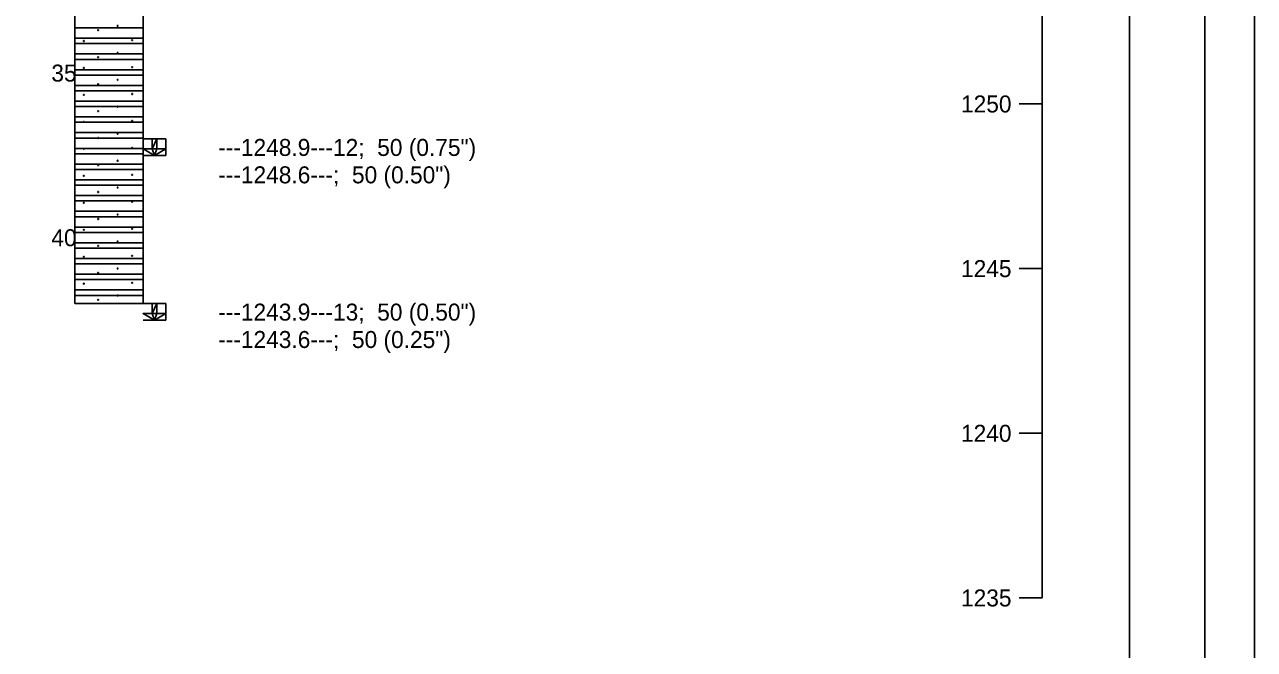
# Model space of a CAD drawing. Extents: x 2150148.6 to 2150220.1, y 143803.7 to 143875.1.
# Drawn here: x 2150191.59 to 2150200.57, y 143815.4 to 143819.96 of the extents above; entities that cross this region are included whole.
import ezdxf

# ---------------------------------------------------------------- set-up
doc = ezdxf.new("R2010")
doc.units = 0
for name, color, linetype in [('Default', 7, 'Continuous'), ('SHT_Plot_Shape_Full', 7, 'Continuous'), ('SHT_Plot_Shape_Half', 7, 'Continuous'), ('SHT_Sheet_Border', 7, 'Continuous')]:
    doc.layers.add(name, color=color, linetype=linetype)

msp = doc.modelspace()

# ---------------------------------------------------------------- linework, layer by layer
at = {"layer": 'Default'}
msp.add_line((2150199.0247, 143815.7727), (2150199.0247, 143828.9938), dxfattribs=at)
for points in [[(2150191.9604, 143828.0174), (2150191.9604, 143817.9213)], [(2150192.4604, 143828.0174), (2150192.4604, 143817.9213)], [(2150191.9604, 143819.9337), (2150192.4604, 143819.9337)], [(2150192.1355, 143819.9172), (2150192.1338, 143819.9201), (2150192.1306, 143819.9201), (2150192.1289, 143819.9173), (2150192.1306, 143819.9144), (2150192.1338, 143819.9144), (2150192.1355, 143819.9172)], [(2150192.2781, 143819.9491), (2150192.2764, 143819.9519), (2150192.2731, 143819.9519), (2150192.2715, 143819.9491), (2150192.2731, 143819.9463), (2150192.2764, 143819.9463), (2150192.2781, 143819.9491)], [(2150191.9604, 143819.8582), (2150192.4604, 143819.8582)], [(2150192.0308, 143819.8383), (2150192.0292, 143819.8411), (2150192.0259, 143819.8411), (2150192.0243, 143819.8383), (2150192.0259, 143819.8354), (2150192.0292, 143819.8354), (2150192.0308, 143819.8383)], [(2150192.3836, 143819.8448), (2150192.3819, 143819.8477), (2150192.3787, 143819.8477), (2150192.377, 143819.8448), (2150192.3787, 143819.8419), (2150192.3819, 143819.8419), (2150192.3836, 143819.8448)], [(2150191.9604, 143819.8188), (2150192.4604, 143819.8188)], [(2150191.9604, 143819.7434), (2150192.4604, 143819.7434)], [(2150192.2781, 143819.7522), (2150192.2764, 143819.7551), (2150192.2731, 143819.7551), (2150192.2715, 143819.7522), (2150192.2731, 143819.7494), (2150192.2764, 143819.7494), (2150192.2781, 143819.7522)], [(2150191.9604, 143819.704), (2150192.4604, 143819.704)], [(2150192.0308, 143819.6414), (2150192.0292, 143819.6442), (2150192.0259, 143819.6442), (2150192.0243, 143819.6414), (2150192.0259, 143819.6385), (2150192.0292, 143819.6385), (2150192.0308, 143819.6414)], [(2150192.1355, 143819.7204), (2150192.1338, 143819.7232), (2150192.1306, 143819.7232), (2150192.1289, 143819.7204), (2150192.1306, 143819.7175), (2150192.1338, 143819.7175), (2150192.1355, 143819.7204)], [(2150192.3836, 143819.6479), (2150192.3819, 143819.6508), (2150192.3787, 143819.6508), (2150192.377, 143819.6479), (2150192.3787, 143819.6451), (2150192.3819, 143819.6451), (2150192.3836, 143819.6479)], [(2150191.9604, 143819.6286), (2150192.4604, 143819.6286)], [(2150191.9604, 143819.5892), (2150192.4604, 143819.5892)], [(2150192.2781, 143819.5554), (2150192.2764, 143819.5582), (2150192.2731, 143819.5582), (2150192.2715, 143819.5554), (2150192.2731, 143819.5526), (2150192.2764, 143819.5526), (2150192.2781, 143819.5554)], [(2150191.9604, 143819.5137), (2150192.4604, 143819.5137)], [(2150191.9604, 143819.4744), (2150192.4604, 143819.4744)], [(2150192.1355, 143819.5235), (2150192.1338, 143819.5264), (2150192.1306, 143819.5264), (2150192.1289, 143819.5236), (2150192.1306, 143819.5207), (2150192.1338, 143819.5207), (2150192.1355, 143819.5235)], [(2150191.9604, 143819.3989), (2150192.4604, 143819.3989)], [(2150192.0308, 143819.4446), (2150192.0292, 143819.4474), (2150192.0259, 143819.4474), (2150192.0243, 143819.4446), (2150192.0259, 143819.4417), (2150192.0292, 143819.4417), (2150192.0308, 143819.4446)], [(2150192.3836, 143819.4511), (2150192.3819, 143819.454), (2150192.3787, 143819.454), (2150192.377, 143819.4511), (2150192.3787, 143819.4482), (2150192.3819, 143819.4482), (2150192.3836, 143819.4511)], [(2150199.0247, 143819.3785), (2150198.858, 143819.3785)], [(2150191.9604, 143819.3595), (2150192.4604, 143819.3595)], [(2150191.9604, 143819.2841), (2150192.4604, 143819.2841)], [(2150192.1355, 143819.3267), (2150192.1338, 143819.3295), (2150192.1306, 143819.3295), (2150192.1289, 143819.3267), (2150192.1306, 143819.3238), (2150192.1338, 143819.3238), (2150192.1355, 143819.3267)], [(2150192.2781, 143819.3585), (2150192.2764, 143819.3614), (2150192.2731, 143819.3614), (2150192.2715, 143819.3585), (2150192.2731, 143819.3557), (2150192.2764, 143819.3557), (2150192.2781, 143819.3585)], [(2150191.9604, 143819.2447), (2150192.4604, 143819.2447)], [(2150192.0308, 143819.2477), (2150192.0292, 143819.2505), (2150192.0259, 143819.2505), (2150192.0243, 143819.2477), (2150192.0259, 143819.2448), (2150192.0292, 143819.2448), (2150192.0308, 143819.2477)], [(2150192.3836, 143819.2542), (2150192.3819, 143819.2571), (2150192.3787, 143819.2571), (2150192.377, 143819.2542), (2150192.3787, 143819.2514), (2150192.3819, 143819.2514), (2150192.3836, 143819.2542)], [(2150191.9604, 143819.1692), (2150192.4604, 143819.1692)], [(2150191.9604, 143819.1299), (2150192.4604, 143819.1299)], [(2150192.1355, 143819.1298), (2150192.1338, 143819.1327), (2150192.1306, 143819.1327), (2150192.1289, 143819.1299), (2150192.1306, 143819.127), (2150192.1338, 143819.127), (2150192.1355, 143819.1298)], [(2150192.2781, 143819.1617), (2150192.2764, 143819.1645), (2150192.2731, 143819.1645), (2150192.2715, 143819.1617), (2150192.2731, 143819.1589), (2150192.2764, 143819.1589), (2150192.2781, 143819.1617)], [(2150192.4604, 143819.1232), (2150192.6271, 143819.1232)], [(2150192.6271, 143819.003), (2150192.6271, 143819.1232)], [(2150191.9604, 143819.0544), (2150192.4604, 143819.0544)], [(2150191.9604, 143819.015), (2150192.4604, 143819.015)], [(2150192.0308, 143819.0509), (2150192.0292, 143819.0537), (2150192.0259, 143819.0537), (2150192.0243, 143819.0509), (2150192.0259, 143819.048), (2150192.0292, 143819.048), (2150192.0308, 143819.0509)], [(2150192.3836, 143819.0574), (2150192.3819, 143819.0603), (2150192.3787, 143819.0603), (2150192.377, 143819.0574), (2150192.3787, 143819.0545), (2150192.3819, 143819.0545), (2150192.3836, 143819.0574)], [(2150191.9604, 143818.9396), (2150192.4604, 143818.9396)], [(2150192.1355, 143818.933), (2150192.1338, 143818.9358), (2150192.1306, 143818.9358), (2150192.1289, 143818.933), (2150192.1306, 143818.9301), (2150192.1338, 143818.9301), (2150192.1355, 143818.933)], [(2150192.2781, 143818.9648), (2150192.2764, 143818.9677), (2150192.2731, 143818.9677), (2150192.2715, 143818.9648), (2150192.2731, 143818.962), (2150192.2764, 143818.962), (2150192.2781, 143818.9648)], [(2150192.4604, 143819.003), (2150192.6271, 143819.003)], [(2150191.9604, 143818.9002), (2150192.4604, 143818.9002)], [(2150192.0308, 143818.854), (2150192.0292, 143818.8568), (2150192.0259, 143818.8568), (2150192.0243, 143818.854), (2150192.0259, 143818.8511), (2150192.0292, 143818.8511), (2150192.0308, 143818.854)], [(2150192.3836, 143818.8605), (2150192.3819, 143818.8634), (2150192.3787, 143818.8634), (2150192.377, 143818.8605), (2150192.3787, 143818.8577), (2150192.3819, 143818.8577), (2150192.3836, 143818.8605)], [(2150191.9604, 143818.8248), (2150192.4604, 143818.8248)], [(2150191.9604, 143818.7854), (2150192.4604, 143818.7854)], [(2150192.2781, 143818.768), (2150192.2764, 143818.7708), (2150192.2731, 143818.7708), (2150192.2715, 143818.768), (2150192.2731, 143818.7652), (2150192.2764, 143818.7652), (2150192.2781, 143818.768)], [(2150191.9604, 143818.7099), (2150192.4604, 143818.7099)], [(2150191.9604, 143818.6706), (2150192.4604, 143818.6706)], [(2150192.0308, 143818.6572), (2150192.0292, 143818.66), (2150192.0259, 143818.66), (2150192.0243, 143818.6572), (2150192.0259, 143818.6543), (2150192.0292, 143818.6543), (2150192.0308, 143818.6572)], [(2150192.1355, 143818.7361), (2150192.1338, 143818.739), (2150192.1306, 143818.739), (2150192.1289, 143818.7362), (2150192.1306, 143818.7333), (2150192.1338, 143818.7333), (2150192.1355, 143818.7361)], [(2150192.3836, 143818.6637), (2150192.3819, 143818.6666), (2150192.3787, 143818.6666), (2150192.377, 143818.6637), (2150192.3787, 143818.6608), (2150192.3819, 143818.6608), (2150192.3836, 143818.6637)], [(2150191.9604, 143818.5951), (2150192.4604, 143818.5951)], [(2150192.2781, 143818.5711), (2150192.2764, 143818.574), (2150192.2731, 143818.574), (2150192.2715, 143818.5711), (2150192.2731, 143818.5683), (2150192.2764, 143818.5683), (2150192.2781, 143818.5711)], [(2150191.9604, 143818.5557), (2150192.4604, 143818.5557)], [(2150191.9604, 143818.4803), (2150192.4604, 143818.4803)], [(2150192.1355, 143818.5393), (2150192.1338, 143818.5421), (2150192.1306, 143818.5421), (2150192.1289, 143818.5393), (2150192.1306, 143818.5364), (2150192.1338, 143818.5364), (2150192.1355, 143818.5393)], [(2150191.9604, 143818.4409), (2150192.4604, 143818.4409)], [(2150192.0308, 143818.4603), (2150192.0292, 143818.4631), (2150192.0259, 143818.4631), (2150192.0243, 143818.4603), (2150192.0259, 143818.4574), (2150192.0292, 143818.4574), (2150192.0308, 143818.4603)], [(2150192.3836, 143818.4668), (2150192.3819, 143818.4697), (2150192.3787, 143818.4697), (2150192.377, 143818.4668), (2150192.3787, 143818.464), (2150192.3819, 143818.464), (2150192.3836, 143818.4668)], [(2150191.9604, 143818.3654), (2150192.4604, 143818.3654)], [(2150191.9604, 143818.3261), (2150192.4604, 143818.3261)], [(2150192.1355, 143818.3424), (2150192.1338, 143818.3453), (2150192.1306, 143818.3453), (2150192.1289, 143818.3425), (2150192.1306, 143818.3396), (2150192.1338, 143818.3396), (2150192.1355, 143818.3424)], [(2150192.2781, 143818.3743), (2150192.2764, 143818.3771), (2150192.2731, 143818.3771), (2150192.2715, 143818.3743), (2150192.2731, 143818.3715), (2150192.2764, 143818.3715), (2150192.2781, 143818.3743)], [(2150191.9604, 143818.2506), (2150192.4604, 143818.2506)], [(2150191.9604, 143818.2112), (2150192.4604, 143818.2112)], [(2150192.0308, 143818.2635), (2150192.0292, 143818.2663), (2150192.0259, 143818.2663), (2150192.0243, 143818.2635), (2150192.0259, 143818.2606), (2150192.0292, 143818.2606), (2150192.0308, 143818.2635)], [(2150192.3836, 143818.27), (2150192.3819, 143818.2729), (2150192.3787, 143818.2729), (2150192.377, 143818.27), (2150192.3787, 143818.2671), (2150192.3819, 143818.2671), (2150192.3836, 143818.27)], [(2150191.9604, 143818.1358), (2150192.4604, 143818.1358)], [(2150192.1355, 143818.1456), (2150192.1338, 143818.1484), (2150192.1306, 143818.1484), (2150192.1289, 143818.1456), (2150192.1306, 143818.1427), (2150192.1338, 143818.1427), (2150192.1355, 143818.1456)], [(2150192.2781, 143818.1774), (2150192.2764, 143818.1803), (2150192.2731, 143818.1803), (2150192.2715, 143818.1774), (2150192.2731, 143818.1746), (2150192.2764, 143818.1746), (2150192.2781, 143818.1774)], [(2150199.0247, 143818.1766), (2150198.858, 143818.1766)], [(2150191.9604, 143818.0964), (2150192.4604, 143818.0964)], [(2150192.0308, 143818.0666), (2150192.0292, 143818.0694), (2150192.0259, 143818.0694), (2150192.0243, 143818.0666), (2150192.0259, 143818.0637), (2150192.0292, 143818.0637), (2150192.0308, 143818.0666)], [(2150192.3836, 143818.0731), (2150192.3819, 143818.076), (2150192.3787, 143818.076), (2150192.377, 143818.0731), (2150192.3787, 143818.0703), (2150192.3819, 143818.0703), (2150192.3836, 143818.0731)], [(2150191.9604, 143818.021), (2150192.4604, 143818.021)], [(2150191.9604, 143817.9816), (2150192.4604, 143817.9816)], [(2150192.1355, 143817.9487), (2150192.1338, 143817.9516), (2150192.1306, 143817.9516), (2150192.1289, 143817.9488), (2150192.1306, 143817.9459), (2150192.1338, 143817.9459), (2150192.1355, 143817.9487)], [(2150192.2781, 143817.9806), (2150192.2764, 143817.9834), (2150192.2731, 143817.9834), (2150192.2715, 143817.9806), (2150192.2731, 143817.9778), (2150192.2764, 143817.9778), (2150192.2781, 143817.9806)], [(2150191.9604, 143817.9213), (2150192.4604, 143817.9213)], [(2150192.4604, 143817.9213), (2150192.6271, 143817.9213)], [(2150192.6271, 143817.8011), (2150192.6271, 143817.9213)], [(2150192.4604, 143817.8011), (2150192.6271, 143817.8011)], [(2150199.0247, 143816.9746), (2150198.858, 143816.9746)], [(2150199.0247, 143815.7727), (2150198.858, 143815.7727)]]:
    msp.add_lwpolyline(points, dxfattribs=at)
for points in [[(2150192.5271, 143819.0511), (2150192.5604, 143819.0511), (2150192.5604, 143819.1232), (2150192.5271, 143819.0511)], [(2150192.5271, 143819.0511), (2150192.5604, 143819.1232), (2150192.5271, 143819.1232), (2150192.5271, 143819.0511)], [(2150192.5271, 143819.0511), (2150192.4604, 143819.0511), (2150192.5437, 143819.003), (2150192.5271, 143819.0511)], [(2150192.5271, 143819.0511), (2150192.5437, 143819.003), (2150192.5604, 143819.0511), (2150192.5271, 143819.0511)], [(2150192.5437, 143819.003), (2150192.6271, 143819.0511), (2150192.5604, 143819.0511), (2150192.5437, 143819.003)], [(2150192.5271, 143817.8491), (2150192.4604, 143817.8491), (2150192.5437, 143817.8011), (2150192.5271, 143817.8491)], [(2150192.5271, 143817.8491), (2150192.5604, 143817.8491), (2150192.5604, 143817.9213), (2150192.5271, 143817.8491)], [(2150192.5271, 143817.8491), (2150192.5604, 143817.9213), (2150192.5271, 143817.9213), (2150192.5271, 143817.8491)], [(2150192.5271, 143817.8491), (2150192.5437, 143817.8011), (2150192.5604, 143817.8491), (2150192.5271, 143817.8491)], [(2150192.5437, 143817.8011), (2150192.6271, 143817.8491), (2150192.5604, 143817.8491), (2150192.5437, 143817.8011)]]:
    msp.add_lwpolyline(points, close=True, dxfattribs=at)
at = {"layer": 'SHT_Plot_Shape_Full'}
msp.add_lwpolyline([(2150164.5749, 143833.6878), (2150200.5749, 143833.6878), (2150200.5749, 143809.6878), (2150164.5749, 143809.6878)], close=True, dxfattribs=at)
at = {"layer": 'SHT_Plot_Shape_Half'}
msp.add_lwpolyline([(2150166.2125, 143832.8628), (2150200.2125, 143832.8628), (2150200.2125, 143810.8628), (2150166.2125, 143810.8628)], close=True, dxfattribs=at)
at = {"layer": 'SHT_Sheet_Border'}
msp.add_lwpolyline([(2150199.6625, 143811.3628), (2150168.1625, 143811.3628), (2150168.1625, 143832.3628), (2150199.6625, 143832.3628)], close=True, dxfattribs=at)

# ---------------------------------------------------------------- texts
at = {"layer": 'Default'}
for s, p in [('35', (2150191.79, 143819.542)), ('1250', (2150198.4325, 143819.3165)), ('---1248.9---12;  50 (0.75")', (2150193.0084, 143818.9992)), ('---1248.6---;  50 (0.50")', (2150193.0084, 143818.7992)), ('40', (2150191.79, 143818.34)), ('1245', (2150198.4325, 143818.1146)), ('---1243.9---13;  50 (0.50")', (2150193.0084, 143817.7973)), ('---1243.6---;  50 (0.25")', (2150193.0084, 143817.5973)), ('1240', (2150198.4325, 143816.9126)), ('1235', (2150198.4325, 143815.7107))]:
    msp.add_text(s, height=0.124, dxfattribs=at).set_placement(p)

doc.saveas('drawing.dxf')
